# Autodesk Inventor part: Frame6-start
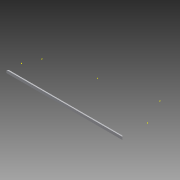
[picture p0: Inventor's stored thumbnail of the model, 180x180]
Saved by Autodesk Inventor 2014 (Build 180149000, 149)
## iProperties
Created: 2009-05
Part Number: Frame6-start
Document SubType Name: Modeling
Designer: millerpa
Density: 1 g/cm^3
Material: Generic
Appearance: Default
Author: millerpa
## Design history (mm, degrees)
derived "Skeleton-frame-start.ipt"
  sketch "Sketch7"
    geometry: L1 (-19.05, -44.45)-(19.05, -44.45) reference; L2 (19.05, -44.45)-(19.05, 44.45) reference; L3 (19.05, 44.45)-(-19.05, 44.45) reference; L4 (-19.05, 44.45)-(-19.05, -44.45) reference; 7 further points
  workplane "Work Plane1"
  workplane "Work Plane2"
  workplane "Work Plane3"
  workplane "Work Plane4"
  workplane "Work Plane5"
  workplane "Work Plane6"
extrude "Extrusion1" new body sketch "Sketch7" stored distance "d4" = 10; taper "d6" = 0 deg
body "Solid1"
feature "Srf5::Skeleton-frame-start.ipt"
body "Srf1"
feature "Srf6::Skeleton-frame-start.ipt"
body "Srf2"
other parameters: "d52" = 45 deg, "d53" = 45 deg, "d0_1" = 3772.27615, "d1" = 914.4, "d2" = 1662.8558, "d26" = 38.1, "d27" = 88.9, "d28" = 19.05, "d29" = 44.45, "d30" = 76.2, "d31" = 127, "d32" = 38.1, "d33" = 88.9, "d34" = 19.05, "d35" = 44.45, "d36" = 76.2, "d37" = 127, "d38" = 38.1, "d39" = 88.9, "d40" = 19.05, "d41" = 44.45, "d42" = 76.2, "d43" = 127, "d44" = 38.1, "d45" = 88.9, "d46" = 19.05, "d47" = 44.45, "d48" = 76.2, "d49" = 127, "d3" = 14.25776, "d5" = 14.25776, "d7" = 14.25776, "d8" = 14.25776, "d9" = 304.8, "d10" = 304.8, "FrameW" = 38.1, "FrameH" = 88.9, "d12" = 38.1, "d13" = 88.9, "d14" = 19.05, "d15" = 44.45, "d16" = 38.1, "d17" = 88.9, "d18" = 19.05, "d19" = 44.45, "d20" = 76.2, "d21" = 127
